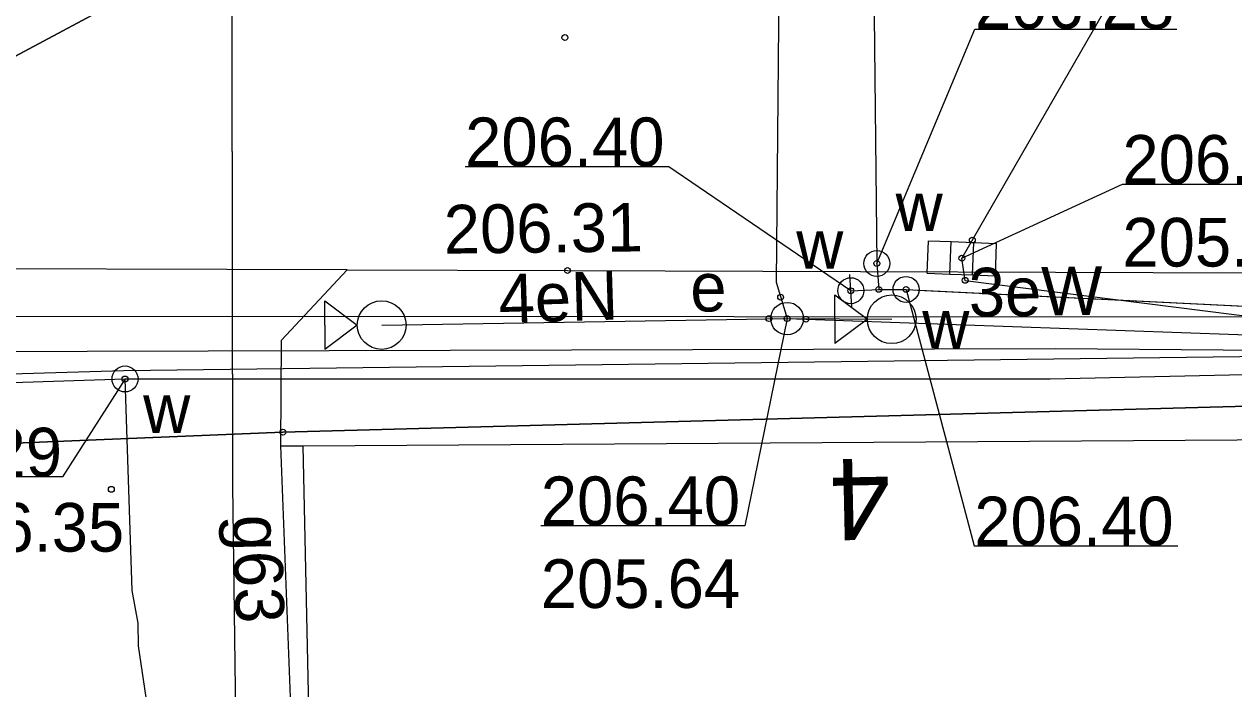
# Model space of a CAD drawing. Extents: x 6512400 to 6513200, y 6022500 to 6022750.
# Drawn here: x 6512764.26 to 6512782.87, y 6022670.32 to 6022680.56 of the extents above; entities that cross this region are included whole.
import ezdxf

# ---------------------------------------------------------------- set-up
doc = ezdxf.new("R2010")
doc.units = 0
for name, color, linetype in [('203-punkt graniczny', 7, 'Continuous'), ('216-obręb ewidencyjny', 7, 'Continuous'), ('218-kontur użytku gruntowego', 7, 'Continuous'), ('219-działka ewidencyjna', 7, 'Continuous'), ('238-Punkt adresowy budynku', 7, 'Continuous'), ('312-budynek ewidencyjny', 7, 'Continuous'), ('chodnik', 7, 'Continuous'), ('chodnik (powierzchnia)', 7, 'Continuous'), ('inna obudowa przewodu - sieć elektroenergetyczna (linia)', 7, 'Continuous'), ('inna obudowa przewodu - sieć gazowa (linia)', 7, 'Continuous'), ('inna obudowa przewodu - sieć wodociągowa (linia)', 7, 'Continuous'), ('kratka ściekowa (punkt)', 7, 'Continuous'), ('krawężnik (linia)', 7, 'Continuous'), ('pikieta sztuczna', 7, 'Continuous'), ('pikieta sztuczna-Atr2', 7, 'Continuous'), ('przewód elektroenergetyczny (linia)', 7, 'Continuous'), ('przewód elektroenergetyczny (linia)-Atr1', 7, 'Continuous'), ('przewód elektroenergetyczny niskiego napięcia (linia)', 7, 'Continuous'), ('przewód gazowy (linia)', 7, 'Continuous'), ('przewód gazowy (linia)-Atr1', 7, 'Continuous'), ('przewód kanalizacyjny (linia)', 7, 'Continuous'), ('przewód wodociągowy (linia)', 7, 'Continuous'), ('punkt o określonej wysokości (sieć elektroenergetyczna)', 7, 'Continuous'), ('punkt o określonej wysokości (sieć elektroenergetyczna)-Atr2', 7, 'Continuous'), ('punkt o określonej wysokości (sieć elektroenergetyczna)-Atr3', 7, 'Continuous'), ('punkt o określonej wysokości (sieć kanalizacyjna)', 7, 'Continuous'), ('punkt o określonej wysokości (sieć kanalizacyjna)-Atr2', 7, 'Continuous'), ('punkt o określonej wysokości (sieć kanalizacyjna)-Atr3', 7, 'Continuous'), ('punkt o określonej wysokości (sieć wodociągowa)', 7, 'Continuous'), ('punkt o określonej wysokości (sieć wodociągowa)-Atr2', 7, 'Continuous'), ('punkt wysokościowy sztuczny', 7, 'Continuous'), ('punkt wysokościowy sztuczny-Atr2', 7, 'Continuous'), ('punkt zmiany cech lub źródła danych o położeniu przewodu (sieć wodociągowa)', 7, 'Continuous'), ('sygnalizator świetlny (punkt)', 7, 'Continuous'), ('właz okrągły - siec elektroenergetyczna (punkt)', 7, 'Continuous'), ('właz okrągły - siec elektroenergetyczna (punkt)-Atr17', 7, 'Continuous'), ('zasuwa - siec wodociągowa (punkt)', 7, 'Continuous'), ('zasuwa - siec wodociągowa (punkt)-Atr17', 7, 'Continuous')]:
    doc.layers.add(name, color=color, linetype=linetype)

# ---------------------------------------------------------------- blocks, each defined once
blk = doc.blocks.new('203')
blk.add_circle((0, 0), 0.045)
blk = doc.blocks.new('PW01')
blk.add_circle((0, 0), 0.045)
blk = doc.blocks.new('US05')
for p, q in [((-0.525, -0.25), (-0.525, 0.25)), ((-0.525, 0.25), (-0.175, 0.25)), ((-0.175, -0.25), (-0.175, 0.25)), ((-0.175, 0.25), (0.175, 0.25)), ((0.175, -0.25), (0.175, 0.25)), ((0.175, 0.25), (0.525, 0.25)), ((0.525, -0.25), (0.525, 0.25)), ((-0.525, -0.25), (-0.175, -0.25)), ((-0.175, -0.25), (0.175, -0.25)), ((0.175, -0.25), (0.525, -0.25))]:
    blk.add_line(p, q)
blk = doc.blocks.new('US16')
for p, q in [((-0.875, 0), (-0.875, 0.375)), ((-0.875, 0.375), (-0.375, 0)), ((-0.875, 0), (-0.875, -0.375)), ((-0.375, 0), (-0.875, -0.375))]:
    blk.add_line(p, q)
blk.add_circle((0, 0), 0.375)
blk = doc.blocks.new('XX_01')
blk.add_line((0, -0.25), (0, 0.25))
blk = doc.blocks.new('US25')
blk.add_circle((0, 0), 0.2)
blk = doc.blocks.new('US22')
blk.add_circle((0, 0), 0.25)
blk = doc.blocks.new('PW02')
blk.add_circle((0, 0), 0.045)

msp = doc.modelspace()

# ---------------------------------------------------------------- linework, layer by layer
at = {"layer": '216-obręb ewidencyjny'}
for points in [[(6512688.62, 6022674.91), (6512702.58, 6022674.18), (6512725.78, 6022672.95), (6512730.35, 6022672.71), (6512735.76, 6022672.94), (6512745.51, 6022673.33), (6512754.87, 6022673.72), (6512768.24, 6022674.27), (6512785.56, 6022674.74), (6512790.49, 6022674.74), (6512796.96, 6022674.74), (6512801.96, 6022670.34), (6512828.67, 6022670.98), (6512833.61, 6022675.02), (6512836.69, 6022675.17), (6512851.94, 6022675.93)], [(6512785.56, 6022674.74), (6512768.24, 6022674.27), (6512754.87, 6022673.72), (6512745.51, 6022673.33), (6512735.76, 6022672.94), (6512730.35, 6022672.71), (6512725.78, 6022672.95), (6512702.575, 6022674.177)]]:
    msp.add_lwpolyline(points, dxfattribs=at)
at = {"layer": '218-kontur użytku gruntowego'}
for points in [[(6512785.56, 6022674.74), (6512768.24, 6022674.27)], [(6512768.24, 6022674.27), (6512785.56, 6022674.74)], [(6512768.24, 6022674.27), (6512754.87, 6022673.72)], [(6512754.87, 6022673.72), (6512768.24, 6022674.27)]]:
    msp.add_lwpolyline(points, dxfattribs=at)
at = {"layer": '219-działka ewidencyjna'}
for points in [[(6512785.56, 6022674.74), (6512768.24, 6022674.27)], [(6512768.24, 6022674.27), (6512754.87, 6022673.72)]]:
    msp.add_lwpolyline(points, dxfattribs=at)
at = {"layer": '312-budynek ewidencyjny'}
for points in [[(6512768.55, 6022674.06), (6512785.32, 6022674.17)], [(6512768.68, 6022668.12), (6512768.55, 6022674.06)]]:
    msp.add_lwpolyline(points, dxfattribs=at)
at = {"layer": 'chodnik'}
msp.add_lwpolyline([(6512768.44, 6022668.05), (6512768.21, 6022674.06), (6512768.22, 6022675.69), (6512769.23, 6022676.77), (6512761.81, 6022676.79), (6512762.96, 6022675.7), (6512762.9, 6022674.52), (6512762.83, 6022671.34), (6512755.26, 6022671.25), (6512745.44, 6022671.27), (6512745.37, 6022673.33), (6512745.36, 6022673.75), (6512745.04, 6022673.58), (6512744.23, 6022673.02), (6512743.49, 6022672.33), (6512742.93, 6022671.51), (6512742.59, 6022670.47), (6512743.54, 6022669.87)], dxfattribs=at)
at = {"layer": 'chodnik (powierzchnia)'}
msp.add_lwpolyline([(6512768.21, 6022674.06), (6512768.55, 6022674.06), (6512785.32, 6022674.17), (6512797.05, 6022674.74)], dxfattribs=at)
at = {"layer": 'inna obudowa przewodu - sieć elektroenergetyczna (linia)'}
msp.add_lwpolyline([(6512775.92, 6022686.23), (6512775.83, 6022676.58), (6512775.83, 6022676.57)], dxfattribs=at)
at = {"layer": 'inna obudowa przewodu - sieć gazowa (linia)'}
msp.add_lwpolyline([(6512767.47, 6022673.46), (6512767.45, 6022687.17), (6512767.45, 6022687.18)], dxfattribs=at)
at = {"layer": 'inna obudowa przewodu - sieć wodociągowa (linia)'}
msp.add_lwpolyline([(6512778.01, 6022676.46), (6512787.32, 6022676)], dxfattribs=at)
at = {"layer": 'krawężnik (linia)'}
msp.add_lwpolyline([(6512769.23, 6022676.77), (6512772.62, 6022676.76), (6512796.66, 6022676.68), (6512798.51, 6022676.57), (6512799.61, 6022676.46)], dxfattribs=at)
at = {"layer": 'przewód elektroenergetyczny (linia)'}
for points in [[(6512775.84, 6022688.03), (6512775.92, 6022686.23), (6512775.83, 6022676.58), (6512776, 6022676.02)], [(6512731.37, 6022676.71), (6512731.37, 6022675.58), (6512748.46, 6022675.47), (6512780.13, 6022675.56), (6512787.87, 6022675.5)], [(6512702.569, 6022673.878), (6512710.28, 6022673.25), (6512716.66, 6022675.97), (6512746.13, 6022674.3), (6512752.79, 6022674.32), (6512760.61, 6022675.35), (6512763.38, 6022676.06), (6512798.79, 6022676.04)], [(6512769.76, 6022675.92), (6512776, 6022676.02)], [(6512776, 6022676.02), (6512799.41, 6022675.19), (6512801.88, 6022673.76), (6512804.18, 6022672.41), (6512807.52, 6022669.86), (6512808.59, 6022669.6), (6512810.5, 6022669.85), (6512831.73, 6022668.71)], [(6512776, 6022676.02), (6512777.61, 6022676.01)], [(6512702.603, 6022675.567), (6512731.84, 6022674.22), (6512765.79, 6022675.22), (6512787.87, 6022675.5)]]:
    msp.add_lwpolyline(points, dxfattribs=at)
at = {"layer": 'przewód elektroenergetyczny niskiego napięcia (linia)'}
for points in [[(6512751.03, 6022673.06), (6512782.09, 6022689.68)], [(6512782.09, 6022689.68), (6512751.03, 6022673.06)]]:
    msp.add_lwpolyline(points, dxfattribs=at)
at = {"layer": 'przewód gazowy (linia)'}
msp.add_lwpolyline([(6512770.64, 6022666.75), (6512770.33, 6022666.62), (6512769.61, 6022665.73), (6512768.94, 6022665.81), (6512767.54, 6022667.96), (6512767.47, 6022673.45), (6512767.45, 6022687.17), (6512767.44, 6022687.59)], dxfattribs=at)
at = {"layer": 'przewód kanalizacyjny (linia)'}
for points in [[(6512782.79, 6022684.08), (6512778.69, 6022676.95)], [(6512794.49, 6022674.61), (6512778.74, 6022676.6), (6512778.69, 6022676.95)]]:
    msp.add_lwpolyline(points, dxfattribs=at)
at = {"layer": 'przewód wodociągowy (linia)'}
for points in [[(6512777.27, 6022686.75), (6512777.28, 6022686.41), (6512777.38, 6022676.87), (6512777.41, 6022676.47)], [(6512776.98, 6022676.45), (6512777.41, 6022676.47), (6512777.83, 6022676.47), (6512787.32, 6022676), (6512787.61, 6022675.99), (6512796.6, 6022675.55), (6512799.85, 6022675.39), (6512814.29, 6022667.35), (6512815.22, 6022667.12), (6512815.2, 6022666.73), (6512814.74, 6022665.5)], [(6512702.579, 6022674.359), (6512731.63, 6022673.98), (6512765.81, 6022675.09), (6512780.05, 6022675.09), (6512787.64, 6022675.26)], [(6512766.79, 6022665.75), (6512766.02, 6022670.98), (6512766.01, 6022671.33), (6512765.92, 6022671.83), (6512765.81, 6022675.09)]]:
    msp.add_lwpolyline(points, dxfattribs=at)
at = {"layer": 'punkt o określonej wysokości (sieć elektroenergetyczna)-Atr2'}
msp.add_lwpolyline([(6512776, 6022676.02), (6512775.35, 6022672.83), (6512772.209, 6022672.83)], dxfattribs=at)
at = {"layer": 'punkt o określonej wysokości (sieć kanalizacyjna)-Atr2'}
msp.add_lwpolyline([(6512778.69, 6022676.95), (6512781.16, 6022678.09), (6512784.269, 6022678.09)], dxfattribs=at)
at = {"layer": 'punkt o określonej wysokości (sieć wodociągowa)-Atr2'}
for points in [[(6512777.38, 6022676.87), (6512778.89, 6022680.48), (6512781.999, 6022680.48)], [(6512776.98, 6022676.45), (6512774.18, 6022678.36), (6512771.045, 6022678.36)], [(6512777.83, 6022676.47), (6512778.88, 6022672.52), (6512782.015, 6022672.52)], [(6512765.81, 6022675.09), (6512764.85, 6022673.58), (6512761.773, 6022673.58)]]:
    msp.add_lwpolyline(points, dxfattribs=at)

# ---------------------------------------------------------------- block references
at = {"layer": '203-punkt graniczny'}
msp.add_blockref('203', (6512768.24, 6022674.27), dxfattribs=at)
at = {"layer": 'kratka ściekowa (punkt)', "rotation": -2.246}
msp.add_blockref('US05', (6512778.69, 6022676.95), dxfattribs=at)
at = {"layer": 'pikieta sztuczna'}
msp.add_blockref('PW01', (6512765.6, 6022673.39), dxfattribs=at)
at = {"layer": 'punkt o określonej wysokości (sieć elektroenergetyczna)'}
for p, rotation in [((6512775.9, 6022676.35), -71.878), ((6512775.72, 6022676.02), 1.744), ((6512776, 6022676.02), 0.356), ((6512776.29, 6022676.01), -1.248)]:
    msp.add_blockref('PW01', p, dxfattribs=dict(at, rotation=rotation))
at = {"layer": 'punkt o określonej wysokości (sieć kanalizacyjna)'}
for p, rotation in [((6512778.85, 6022677.23), 60.912), ((6512778.69, 6022676.95), -2.246), ((6512778.74, 6022676.61), -79.992)]:
    msp.add_blockref('PW01', p, dxfattribs=dict(at, rotation=rotation))
at = {"layer": 'punkt o określonej wysokości (sieć wodociągowa)'}
for p, rotation in [((6512777.38, 6022676.87), -88.618), ((6512776.98, 6022676.45), 3.9910000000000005)]:
    msp.add_blockref('PW01', p, dxfattribs=dict(at, rotation=rotation))
for p in [(6512777.41, 6022676.47), (6512777.83, 6022676.47), (6512765.81, 6022675.09)]:
    msp.add_blockref('PW01', p, dxfattribs=at)
at = {"layer": 'punkt wysokościowy sztuczny'}
for p in [(6512772.58, 6022680.35), (6512772.62, 6022676.76)]:
    msp.add_blockref('PW02', p, dxfattribs=at)
at = {"layer": 'punkt zmiany cech lub źródła danych o położeniu przewodu (sieć wodociągowa)', "rotation": 3.9910000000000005}
msp.add_blockref('XX_01', (6512776.98, 6022676.45), dxfattribs=at)
at = {"layer": 'sygnalizator świetlny (punkt)'}
for p in [(6512769.76, 6022675.92), (6512777.61, 6022676.01)]:
    msp.add_blockref('US16', p, dxfattribs=at)
at = {"layer": 'właz okrągły - siec elektroenergetyczna (punkt)', "rotation": 0.356}
msp.add_blockref('US22', (6512776, 6022676.02), dxfattribs=at)
at = {"layer": 'zasuwa - siec wodociągowa (punkt)'}
for p, rotation in [((6512777.38, 6022676.87), -88.618), ((6512776.98, 6022676.45), 3.9910000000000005)]:
    msp.add_blockref('US25', p, dxfattribs=dict(at, rotation=rotation))
for p in [(6512777.83, 6022676.47), (6512765.81, 6022675.09)]:
    msp.add_blockref('US25', p, dxfattribs=at)

# ---------------------------------------------------------------- texts
at = {"layer": '238-Punkt adresowy budynku'}
msp.add_text('4', height=1.25, rotation=181.198, dxfattribs=at).set_placement((6512777.58, 6022673.87))
at = {"layer": 'pikieta sztuczna-Atr2'}
msp.add_text('206.35', height=0.75, dxfattribs=at).set_placement((6512762.73, 6022672.43))
at = {"layer": 'przewód elektroenergetyczny (linia)-Atr1'}
for s, rotation, p in [('3eW', 0.777, (6512778.8, 6022676.05)), ('4eN', 1.744, (6512771.57, 6022675.95))]:
    msp.add_text(s, height=0.75, rotation=rotation, dxfattribs=at).set_placement(p)
at = {"layer": 'przewód gazowy (linia)-Atr1'}
msp.add_text('g63', height=0.75, rotation=271.565, dxfattribs=at).set_placement((6512767.47, 6022672.99))
at = {"layer": 'punkt o określonej wysokości (sieć elektroenergetyczna)-Atr2'}
msp.add_text('206.40', height=0.75, dxfattribs=at).set_placement((6512772.209, 6022672.838))
at = {"layer": 'punkt o określonej wysokości (sieć elektroenergetyczna)-Atr3'}
msp.add_text('205.64', height=0.75, dxfattribs=at).set_placement((6512772.209, 6022671.562))
at = {"layer": 'punkt o określonej wysokości (sieć kanalizacyjna)-Atr2'}
msp.add_text('206.28', height=0.75, dxfattribs=at).set_placement((6512781.16, 6022678.098))
at = {"layer": 'punkt o określonej wysokości (sieć kanalizacyjna)-Atr3'}
msp.add_text('205.13', height=0.75, dxfattribs=at).set_placement((6512781.16, 6022676.822))
at = {"layer": 'punkt o określonej wysokości (sieć wodociągowa)-Atr2'}
for s, p in [('206.28', (6512778.89, 6022680.488)), ('206.40', (6512771.045, 6022678.368)), ('206.29', (6512761.773, 6022673.588)), ('206.40', (6512778.88, 6022672.527))]:
    msp.add_text(s, height=0.75, dxfattribs=at).set_placement(p)
at = {"layer": 'punkt wysokościowy sztuczny-Atr2'}
msp.add_text('206.31', height=0.75, rotation=0.676, dxfattribs=at).set_placement((6512770.72, 6022677.02))
at = {"layer": 'właz okrągły - siec elektroenergetyczna (punkt)-Atr17'}
msp.add_text('e', height=0.75, dxfattribs=at).set_placement((6512774.51, 6022676.13))
at = {"layer": 'zasuwa - siec wodociągowa (punkt)-Atr17'}
for p in [(6512777.67, 6022677.37), (6512776.14, 6022676.79), (6512778.08, 6022675.56), (6512766.09, 6022674.26)]:
    msp.add_text('w', height=0.75, dxfattribs=at).set_placement(p)

doc.saveas('drawing.dxf')
